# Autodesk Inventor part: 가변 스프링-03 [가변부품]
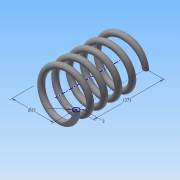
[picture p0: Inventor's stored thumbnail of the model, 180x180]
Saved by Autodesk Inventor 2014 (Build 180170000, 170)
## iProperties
Created: 2015-09
Part Number: 가변 스프링-03 [가변부품]
Material: 강철, 탄소
Document SubType Name: Modeling
Designer: study
Density: 7.87 g/cm^3
Appearance: 반연마
Mass: 18.7976 g
Surface Area: 32.4648 cm^2
Volume: 2.38851 cm^3
Author: study
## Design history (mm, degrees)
sketch "스케치1"
  geometry: L1 (0, 0)-(11, 0); L2 (11, 0)-(11, 29.043); L3 (11, 29.043)-(0, 29.043); L4 (0, 29.043)-(0, 0); C1 r 1.5 at (11, 0)
  constraints: 8 end point, 2 parallel, 1 centre point, 1 coincident, 1 horizontal, 1 perpendicular
  dimensions: "d0" = 3 diameter of C1; "d1" = 29.04259 distance between parallel lines of L3 L1 (derived); "d2" = 22 diameter of L2 L4
feature "코일1" sketch "스케치1" pitch "d3" = 10; turns "d5" = 5; dims "d4" = 29.04259 (= d1), "d6" = 0, angle "d7" = 90 deg, angle "d8" = 90 deg, "d9" = 0, "d10" = 0
node "작업 평면1"
sketch "스케치2"
  geometry: L1 (-12.5, 0)-(-9.5, 0) reference; 1 further point
  constraints: 1 horizontal alignment
extrude "돌출1" cut sketch "스케치2" stored distance "d12" = 10; taper "d13" = 0 deg
node "작업 평면2"
sketch "스케치3"
  geometry: L1 (-9.5, 0)-(-12.5, 0) reference; 1 further point
  constraints: 1 horizontal alignment
extrude "돌출2" cut sketch "스케치3" stored distance "d15" = 10; taper "d16" = 0 deg
node "솔리드1"
node "절단 모서리 투영1"
node "절단 모서리 투영2"
other parameters: "d11" = 0, "d14" = 29.04259 (= d1)
